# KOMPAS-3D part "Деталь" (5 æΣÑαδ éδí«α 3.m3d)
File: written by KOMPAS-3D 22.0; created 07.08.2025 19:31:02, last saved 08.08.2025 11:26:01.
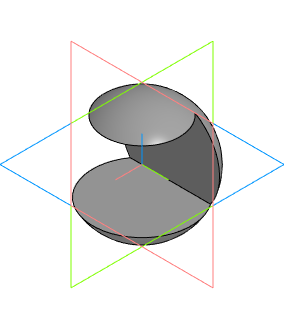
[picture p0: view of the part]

Document properties: Автор: user; Полное имя файла: G:\08 08 пятница\2025 НГ Лаб работы\Лаб 5 Сечения сферы и тора\5 Модели\Сферы Выбор 3.m3d

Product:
- Part/product: Деталь
    Масса: 0.089098

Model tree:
1. Эскиз:1
2. Элемент вращения:1
     Угол 1 = 360
3. Эскиз:2
4. Элемент выдавливания:1
     Расстояние 1 = 20; Расстояние 2 = 20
